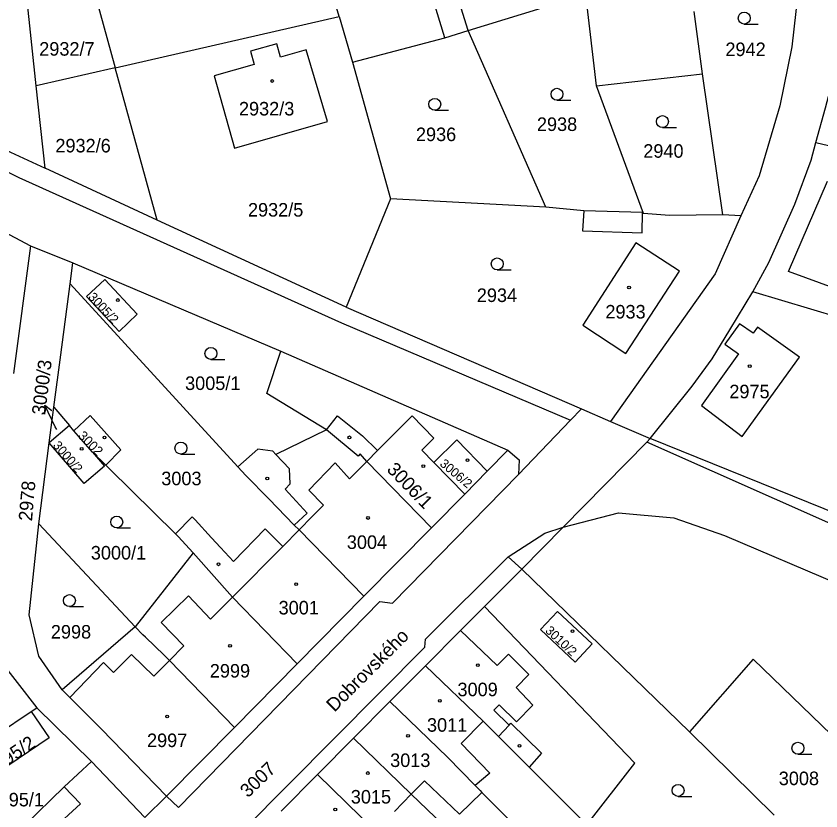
# Model space of a CAD drawing. Extents: x -527335 to -526256, y -1079142 to -1077809.
# Drawn here: x -526682.7 to -526581.6, y -1078714.2 to -1078614.4 of the extents above; entities that cross this region are included whole.
import ezdxf

# ---------------------------------------------------------------- set-up
doc = ezdxf.new("R2010")
doc.units = 0
for name, color, linetype in [('Vrstva 1', 7, 'Continuous'), ('Vrstva 2', 7, 'Continuous'), ('Vrstva 3', 7, 'Continuous'), ('Vrstva 4', 7, 'Continuous'), ('Vrstva 5', 7, 'Continuous'), ('Vrstva 7', 7, 'Continuous')]:
    doc.layers.add(name, color=color, linetype=linetype)

msp = doc.modelspace()

# ---------------------------------------------------------------- linework, layer by layer
at = {"layer": 'Vrstva 1'}
for p, q in [((-526642.16, -1078614.41), (-526648.3, -1078593.48)), ((-526675.77, -1078601.05), (-526670.3, -1078620.85)), ((-526680.21, -1078623.13), (-526682.38, -1078602.87)), ((-526609.83, -1078623.11), (-526611.2, -1078611.62)), ((-526721.35, -1078614.01), (-526679.1, -1078633.49)), ((-526670.3, -1078620.85), (-526642.16, -1078614.41)), ((-526642.16, -1078614.41), (-526640.47, -1078620.16)), ((-526596.5, -1078621.62), (-526597.58, -1078613.8)), ((-526616.19, -1078638.37), (-526625.97, -1078616.19)), ((-526640.47, -1078620.16), (-526635.71, -1078637.32)), ((-526670.3, -1078620.85), (-526680.21, -1078623.13)), ((-526665.02, -1078639.98), (-526670.3, -1078620.85)), ((-526609.83, -1078623.11), (-526596.5, -1078621.62)), ((-526593.98, -1078639.34), (-526596.5, -1078621.62)), ((-526679.1, -1078633.49), (-526680.21, -1078623.13)), ((-526603.92, -1078639.18), (-526609.83, -1078623.11)), ((-526582.29, -1078630.26), (-526567.45, -1078633.62)), ((-526665.02, -1078639.98), (-526679.1, -1078633.49)), ((-526635.71, -1078637.32), (-526641.28, -1078650.93)), ((-526616.19, -1078638.37), (-526635.71, -1078637.32)), ((-526591.7, -1078639.47), (-526593.98, -1078639.34)), ((-526641.28, -1078650.93), (-526665.02, -1078639.98)), ((-526680.92, -1078643.22), (-526683.06, -1078659.24)), ((-526680.92, -1078643.22), (-526675.6, -1078645.35)), ((-526675.97, -1078647.99), (-526675.6, -1078645.35)), ((-526675.6, -1078645.35), (-526649.49, -1078656.45)), ((-526654.89, -1078671), (-526675.97, -1078647.99)), ((-526575.77, -1078653.31), (-526590.18, -1078649.02)), ((-526641.28, -1078650.93), (-526611.73, -1078663.7)), ((-526649.49, -1078656.45), (-526620.98, -1078668.88)), ((-526678.59, -1078667.96), (-526678, -1078663.47)), ((-526678, -1078663.47), (-526676.05, -1078665.78)), ((-526611.73, -1078663.7), (-526608.06, -1078665.29)), ((-526676.05, -1078665.78), (-526678.59, -1078667.96)), ((-526675.49, -1078666.45), (-526676.05, -1078665.78)), ((-526608.06, -1078665.29), (-526603.09, -1078667.44)), ((-526673.15, -1078669.14), (-526675.49, -1078666.45)), ((-526679.91, -1078678.13), (-526678.59, -1078667.96)), ((-526565.26, -1078682.7), (-526603.09, -1078667.44)), ((-526623.55, -1078671.51), (-526620.98, -1078668.88)), ((-526671.47, -1078670.79), (-526673.15, -1078669.14)), ((-526626.37, -1078674.41), (-526623.55, -1078671.51)), ((-526630.57, -1078678.66), (-526626.37, -1078674.41)), ((-526667.79, -1078691.06), (-526679.91, -1078678.13)), ((-526639.06, -1078687.24), (-526647.2, -1078678.89)), ((-526639.06, -1078687.24), (-526630.57, -1078678.66)), ((-526619.22, -1078683.84), (-526614.02, -1078678.55)), ((-526660.52, -1078681.79), (-526667.79, -1078691.06)), ((-526619.22, -1078683.84), (-526623.89, -1078688.51)), ((-526598.14, -1078704.26), (-526619.22, -1078683.84)), ((-526647.44, -1078695.71), (-526639.06, -1078687.24)), ((-526623.89, -1078688.51), (-526626.91, -1078691.53)), ((-526667.79, -1078691.06), (-526676.97, -1078698.98)), ((-526626.91, -1078691.53), (-526631.31, -1078695.96)), ((-526685.78, -1078694.02), (-526680.15, -1078701.23)), ((-526655.33, -1078703.7), (-526647.44, -1078695.71)), ((-526635.79, -1078700.47), (-526631.31, -1078695.96)), ((-526680.84, -1078701.69), (-526680.15, -1078701.23)), ((-526680.15, -1078701.23), (-526673.29, -1078707.97)), ((-526640.35, -1078705.07), (-526635.79, -1078700.47)), ((-526689.86, -1078707.76), (-526680.84, -1078701.69)), ((-526663.87, -1078712.33), (-526655.33, -1078703.7)), ((-526587.53, -1078714.71), (-526598.14, -1078704.26)), ((-526644.88, -1078709.64), (-526640.35, -1078705.07)), ((-526673.29, -1078707.97), (-526666.58, -1078715.02)), ((-526649.43, -1078714.21), (-526644.88, -1078709.64)), ((-526666.58, -1078715.02), (-526663.87, -1078712.33))]:
    msp.add_line(p, q, dxfattribs=at)
for points in [[(-526625.97, -1078616.19), (-526627.66, -1078610.64), (-526633.95, -1078589.47)], [(-526583.43, -1078599.56), (-526584.01, -1078606.72), (-526585.28, -1078618.21), (-526586.79, -1078625.64), (-526589.4, -1078634.43), (-526591.7, -1078639.47)], [(-526582.29, -1078630.26), (-526581.08, -1078625.88), (-526580.12, -1078622.23), (-526579.3, -1078618.4), (-526578.59, -1078614.59), (-526578.22, -1078610.5)], [(-526625.97, -1078616.19), (-526619.24, -1078614.14), (-526611.2, -1078611.62)], [(-526640.47, -1078620.16), (-526628.89, -1078617.08), (-526625.97, -1078616.19)], [(-526646.3, -1078618.62), (-526649.52, -1078619.53), (-526649.99, -1078617.86), (-526653.29, -1078618.79), (-526652.82, -1078620.46), (-526657.87, -1078621.89), (-526655.31, -1078630.94), (-526643.61, -1078627.6), (-526646.3, -1078618.62)], [(-526590.18, -1078649.02), (-526588.18, -1078645.3), (-526584.94, -1078638), (-526582.87, -1078632.45), (-526582.29, -1078630.26)], [(-526697.66, -1078634.2), (-526691.45, -1078637.64), (-526680.92, -1078643.22)], [(-526603.92, -1078639.18), (-526604.04, -1078639.02), (-526611.44, -1078638.83), (-526616.19, -1078638.37)], [(-526591.7, -1078639.47), (-526594.93, -1078646.75), (-526608.06, -1078665.29)], [(-526593.98, -1078639.34), (-526600.67, -1078639.4), (-526603.92, -1078639.18)], [(-526611.54, -1078653.18), (-526606.15, -1078656.74), (-526599.41, -1078646.41), (-526604.88, -1078642.86), (-526611.54, -1078653.18)], [(-526667.52, -1078651.81), (-526669.8, -1078653.97), (-526673.9, -1078649.58), (-526671.6, -1078647.44), (-526667.52, -1078651.81)], [(-526678, -1078663.47), (-526677.14, -1078656.92), (-526675.97, -1078647.99)], [(-526603.09, -1078667.44), (-526597.81, -1078660.87), (-526595.32, -1078657.42), (-526593.1, -1078653.76), (-526590.18, -1078649.02)], [(-526584.32, -1078657.2), (-526589.63, -1078653.45), (-526590.16, -1078654.21), (-526591.86, -1078653.02), (-526593.7, -1078655.57), (-526592, -1078656.79), (-526596.66, -1078663.28), (-526591.53, -1078667.19), (-526584.32, -1078657.2)], [(-526643.76, -1078666.34), (-526651.24, -1078661.76), (-526649.49, -1078656.45)], [(-526620.98, -1078668.88), (-526619.54, -1078670.11), (-526619.63, -1078671.93), (-526613.11, -1078665.14), (-526611.73, -1078663.7)], [(-526671.47, -1078670.79), (-526669.58, -1078668.85), (-526673.46, -1078664.53), (-526675.49, -1078666.45)], [(-526643.76, -1078666.34), (-526650.1, -1078669.43), (-526650.49, -1078669.01), (-526652.4, -1078668.75), (-526654.89, -1078671)], [(-526630.57, -1078678.66), (-526638.7, -1078670.33), (-526639.52, -1078669.35), (-526639.78, -1078669.66), (-526643.76, -1078666.34)], [(-526673.15, -1078669.14), (-526671.65, -1078670.9), (-526674.21, -1078673.09), (-526678.59, -1078667.96)], [(-526626.37, -1078674.41), (-526630.26, -1078670.43), (-526627.38, -1078667.6), (-526623.55, -1078671.51)], [(-526603.09, -1078667.44), (-526603.52, -1078667.88), (-526614.02, -1078678.55)], [(-526662.72, -1078679.38), (-526671.02, -1078671.23), (-526671.47, -1078670.79)], [(-526647.2, -1078678.89), (-526647.8, -1078678.29), (-526651.01, -1078675.02), (-526653.9, -1078672.08), (-526654.89, -1078671)], [(-526614.02, -1078678.55), (-526607.06, -1078676.75), (-526600.12, -1078677.39), (-526593.75, -1078679.6), (-526565.02, -1078691.82), (-526539.54, -1078702.51)], [(-526647.2, -1078678.89), (-526649.26, -1078680.97), (-526651.46, -1078678.78), (-526655.44, -1078682.86), (-526657.06, -1078681.11), (-526658.19, -1078679.88), (-526660.25, -1078677.64), (-526660.62, -1078677.24), (-526662.72, -1078679.38)], [(-526676.97, -1078698.98), (-526679.9, -1078694.76), (-526681.12, -1078689.56), (-526679.91, -1078678.13)], [(-526660.52, -1078681.79), (-526662.37, -1078679.72), (-526662.72, -1078679.38)], [(-526647.44, -1078695.71), (-526655.58, -1078687.34), (-526660.52, -1078681.79)], [(-526611.06, -1078715.96), (-526605, -1078708.2), (-526623.89, -1078688.51)], [(-526616.87, -1078691.41), (-526614.72, -1078689.13), (-526610.38, -1078693.21), (-526612.52, -1078695.5), (-526616.87, -1078691.41)], [(-526655.33, -1078703.7), (-526663.48, -1078695.3), (-526664.15, -1078694.63), (-526666.51, -1078692.39), (-526666.84, -1078692.07), (-526667.79, -1078691.06)], [(-526569.24, -1078715.32), (-526590.17, -1078695.14), (-526598.14, -1078704.26)], [(-526631.31, -1078695.96), (-526624.08, -1078702.91), (-526622.14, -1078704.85), (-526618.3, -1078708.7), (-526611.06, -1078715.96)], [(-526663.87, -1078712.33), (-526672.02, -1078703.91), (-526675.99, -1078699.96), (-526676.97, -1078698.98)], [(-526635.79, -1078700.47), (-526628.55, -1078707.46), (-526625.07, -1078711.01), (-526624.47, -1078711.62), (-526624.22, -1078711.87), (-526622.06, -1078714.05), (-526616.13, -1078720.06), (-526614.38, -1078721.84)], [(-526680.84, -1078701.69), (-526678.6, -1078705.01), (-526687.59, -1078711.07), (-526689.86, -1078707.76)], [(-526640.35, -1078705.07), (-526633.11, -1078712.1), (-526620.07, -1078724.6), (-526618.7, -1078726.19)], [(-526673.29, -1078707.97), (-526676.71, -1078711.19), (-526681.64, -1078715.99), (-526684.49, -1078719.05), (-526685.11, -1078719.62)], [(-526644.88, -1078709.64), (-526637.64, -1078716.69), (-526634.89, -1078719.43), (-526631.42, -1078722.73), (-526630.43, -1078723.74), (-526624.67, -1078729.64), (-526623.18, -1078731.02)]]:
    msp.add_lwpolyline(points, dxfattribs=at)
at = {"layer": 'Vrstva 3'}
for p, q in [((-526591.28, -1078615.37), (-526589.53, -1078615.37)), ((-526614.8, -1078624.94), (-526613.05, -1078624.94)), ((-526630.16, -1078626.2), (-526628.41, -1078626.2)), ((-526601.55, -1078628.37), (-526599.8, -1078628.37)), ((-526622.31, -1078646.25), (-526620.56, -1078646.25)), ((-526658.27, -1078657.49), (-526656.52, -1078657.49)), ((-526662.05, -1078669.38), (-526660.3, -1078669.38)), ((-526670.11, -1078678.66), (-526668.36, -1078678.66)), ((-526676.05, -1078688.53), (-526674.3, -1078688.53)), ((-526584.53, -1078707.07), (-526582.78, -1078707.07)), ((-526599.59, -1078712.37), (-526597.84, -1078712.37))]:
    msp.add_line(p, q, dxfattribs=at)
for centre in [(-526591.28, -1078614.62), (-526614.8, -1078624.19), (-526630.16, -1078625.45), (-526601.55, -1078627.62), (-526622.31, -1078645.5), (-526658.27, -1078656.74), (-526662.05, -1078668.63), (-526670.11, -1078677.91), (-526676.05, -1078687.78), (-526584.53, -1078706.32), (-526599.59, -1078711.62)]:
    msp.add_circle(centre, 0.75, dxfattribs=at)
at = {"layer": 'Vrstva 4'}
for p, q in [((-526628.89, -1078617.08), (-526630.58, -1078611.53)), ((-526720.61, -1078615.59), (-526682.42, -1078634.66)), ((-526682.42, -1078634.66), (-526641.87, -1078652.91)), ((-526585.7, -1078646.44), (-526580.83, -1078635.11)), ((-526611.44, -1078638.83), (-526611.61, -1078641.33)), ((-526604.11, -1078641.6), (-526604.04, -1078639.02)), ((-526611.61, -1078641.33), (-526604.11, -1078641.6)), ((-526579.66, -1078648.66), (-526585.7, -1078646.44)), ((-526641.87, -1078652.91), (-526613.11, -1078665.14)), ((-526643.76, -1078666.34), (-526642.36, -1078664.59)), ((-526642.36, -1078664.59), (-526639.23, -1078667.08)), ((-526633, -1078664.58), (-526634.5, -1078666.09)), ((-526630.26, -1078667.38), (-526633, -1078664.58)), ((-526637.34, -1078668.95), (-526634.5, -1078666.09)), ((-526639.23, -1078667.08), (-526637.34, -1078668.95)), ((-526631.78, -1078668.87), (-526630.26, -1078667.38)), ((-526563.25, -1078685.79), (-526603.52, -1078667.88)), ((-526637.34, -1078668.95), (-526638.7, -1078670.33)), ((-526631.78, -1078668.87), (-526630.26, -1078670.43)), ((-526645.96, -1078673.91), (-526642.68, -1078670.49)), ((-526642.68, -1078670.49), (-526640.85, -1078672.49)), ((-526640.85, -1078672.49), (-526638.7, -1078670.33)), ((-526635.45, -1078688.1), (-526619.63, -1078671.93)), ((-526644.12, -1078675.79), (-526645.96, -1078673.91)), ((-526645.56, -1078677.23), (-526644.12, -1078675.79)), ((-526647.2, -1078678.89), (-526645.56, -1078677.23)), ((-526616.33, -1078679.32), (-526614.02, -1078678.55)), ((-526620.93, -1078682.29), (-526616.33, -1078679.32)), ((-526649.26, -1078680.97), (-526655.58, -1078687.34)), ((-526631.32, -1078692.62), (-526620.93, -1078682.29)), ((-526620.93, -1078682.29), (-526619.22, -1078683.84)), ((-526664.54, -1078690.54), (-526661.08, -1078687.18)), ((-526661.08, -1078687.18), (-526658.32, -1078690.1)), ((-526662.36, -1078713.75), (-526637.04, -1078687.88)), ((-526658.32, -1078690.1), (-526655.58, -1078687.34)), ((-526637.04, -1078687.88), (-526635.45, -1078688.1)), ((-526661.67, -1078693.48), (-526664.54, -1078690.54)), ((-526626.91, -1078691.53), (-526622.33, -1078695.92)), ((-526631.42, -1078693.62), (-526631.32, -1078692.62)), ((-526663.48, -1078695.3), (-526661.67, -1078693.48)), ((-526659.29, -1078721.72), (-526631.42, -1078693.62)), ((-526670.53, -1078696.83), (-526668.27, -1078694.55)), ((-526668.27, -1078694.55), (-526665.46, -1078697.29)), ((-526665.46, -1078697.29), (-526663.48, -1078695.3)), ((-526622.33, -1078695.92), (-526620.9, -1078694.49)), ((-526620.9, -1078694.49), (-526618.33, -1078697.07)), ((-526675.99, -1078699.96), (-526671.78, -1078695.57)), ((-526671.78, -1078695.57), (-526670.53, -1078696.83)), ((-526618.33, -1078697.07), (-526619.92, -1078698.69)), ((-526619.92, -1078698.69), (-526617.83, -1078700.91)), ((-526622.05, -1078700.86), (-526622.72, -1078701.55)), ((-526619.87, -1078702.99), (-526622.05, -1078700.86)), ((-526617.83, -1078700.91), (-526619.87, -1078702.99)), ((-526622.72, -1078701.55), (-526620.81, -1078703.42)), ((-526624.08, -1078702.91), (-526626.85, -1078705.73)), ((-526620.81, -1078703.42), (-526620.58, -1078703.18)), ((-526620.58, -1078703.18), (-526616.74, -1078706.95)), ((-526620.81, -1078703.42), (-526622.14, -1078704.85)), ((-526626.85, -1078705.73), (-526623.23, -1078709.47)), ((-526616.74, -1078706.95), (-526618.3, -1078708.7)), ((-526633.11, -1078712.1), (-526631.46, -1078710.42)), ((-526623.23, -1078709.47), (-526625.07, -1078711.01)), ((-526674.67, -1078713.29), (-526676.71, -1078711.19)), ((-526663.87, -1078712.33), (-526662.36, -1078713.75)), ((-526635.23, -1078714.25), (-526633.11, -1078712.1)), ((-526679.72, -1078717.92), (-526674.67, -1078713.29))]:
    msp.add_line(p, q, dxfattribs=at)
for points in [[(-526647.8, -1078678.29), (-526646.18, -1078676.79), (-526648.96, -1078673.8), (-526648.31, -1078673.13), (-526648.41, -1078671.25), (-526650.1, -1078669.43)], [(-526624.22, -1078711.87), (-526627.03, -1078714.61), (-526631.46, -1078710.42)]]:
    msp.add_lwpolyline(points, dxfattribs=at)
at = {"layer": 'Vrstva 5'}
for centre in [(-526650.58, -1078622.52), (-526605.75, -1078648.47), (-526669.98, -1078650.03), (-526590.59, -1078658.35), (-526671.63, -1078667.29), (-526640.88, -1078667.28), (-526674.51, -1078668.73), (-526626.05, -1078670.14), (-526631.59, -1078670.9), (-526651.19, -1078672.44), (-526638.54, -1078677.4), (-526657.33, -1078683.22), (-526647.56, -1078685.71), (-526612.86, -1078691.61), (-526655.87, -1078693.47), (-526624.74, -1078695.89), (-526629.53, -1078700.37), (-526663.78, -1078702.34), (-526633.51, -1078704.76), (-526619.5, -1078706.03), (-526638.55, -1078709.44), (-526642.65, -1078714.01)]:
    msp.add_circle(centre, 0.175, dxfattribs=at)
at = {"layer": 'Vrstva 7'}
for p, q in [((-526679.15, -1078663.24), (-526679.16, -1078664.36)), ((-526677.83, -1078665.94), (-526679.15, -1078663.24)), ((-526679.15, -1078663.24), (-526678.26, -1078663.92)), ((-526677.65, -1078666.31), (-526677.83, -1078665.94))]:
    msp.add_line(p, q, dxfattribs=at)

# ---------------------------------------------------------------- texts
at = {"layer": 'Vrstva 2'}
for s, p in [('2932/7', (-526679.84, -1078619.34)), ('2942', (-526593.64, -1078619.39)), ('2932/3', (-526654.75, -1078626.85)), ('2938', (-526617.32, -1078628.8)), ('2936', (-526632.52, -1078630.07)), ('2932/6', (-526677.81, -1078631.49)), ('2940', (-526603.96, -1078632.16)), ('2932/5', (-526653.62, -1078639.55)), ('2934', (-526624.87, -1078650.28)), ('2933', (-526608.72, -1078652.35)), ('3005/1', (-526661.52, -1078661.33)), ('2975', (-526593.15, -1078662.37)), ('3003', (-526664.51, -1078673.29)), ('3004', (-526641.2, -1078681.29)), ('3000/1', (-526673.36, -1078682.62)), ('3001', (-526649.77, -1078689.52)), ('2998', (-526678.38, -1078692.55)), ('2999', (-526658.41, -1078697.45)), ('3009', (-526627.3, -1078699.79)), ('3011', (-526631.13, -1078704.25)), ('2997', (-526666.3, -1078706.18)), ('3013', (-526635.76, -1078708.68)), ('3008', (-526586.94, -1078710.96)), ('2995/1', (-526686.2, -1078713.63)), ('3015', (-526640.7, -1078713.27))]:
    msp.add_text(s, height=1.7, dxfattribs=at).set_placement(p)
for s, height, rotation, p in [('3005/2', 1.14, 313, (-526673.76, -1078649.72)), ('3000/3', 1.7, 83, (-526679.1, -1078664.55)), ('3002', 1.2, 315, (-526675.07, -1078667.19)), ('3000/2', 1.14, 311, (-526678.2, -1078668.34)), ('3006/1', 1.7, 314, (-526636.28, -1078671.41)), ('3006/2', 1.139, 320, (-526629.61, -1078670.75)), ('2978', 1.7, 85, (-526680.75, -1078677.85)), ('3010/2', 1.14, 317, (-526616.36, -1078691.67)), ('2995/2', 1.7, 34, (-526685.92, -1078709.94)), ('3007', 1.7, 44, (-526653.62, -1078712.62))]:
    msp.add_text(s, height=height, rotation=rotation, dxfattribs=at).set_placement(p)
at = {"layer": 'Vrstva 7'}
msp.add_text('Dobrovského', height=1.7, rotation=45, dxfattribs=at).set_placement((-526642.75, -1078701.85))

doc.saveas('drawing.dxf')
